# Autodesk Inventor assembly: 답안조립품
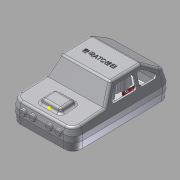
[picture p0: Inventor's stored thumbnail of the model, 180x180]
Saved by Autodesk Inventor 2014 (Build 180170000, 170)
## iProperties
Created: 2015-05
Part Number: 답안조립품
Document SubType Name: Assembly
Designer: Administrator
Author: Administrator
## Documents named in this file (13)
- C:\Documents and Settings\Administrator\바탕 화면\450508V1039\답안조립품.iam
- C:\Documents and Settings\Administrator\바탕 화면\450508V1039\본체.ipt
- C:\Documents and Settings\Administrator\바탕 화면\450508V1039\바퀴.ipt
- C:\Documents and Settings\Administrator\바탕 화면\450508V1039\커버.ipt
- C:\Documents and Settings\Administrator\바탕 화면\450508V1039\바퀴고정부.ipt
- C:\Documents and Settings\Administrator\바탕 화면\450508V1039\M2x4.ipt
- C:\Documents and Settings\Administrator\바탕 화면\450508V1039\바퀴고정부_MIR.ipt
- C:\Documents and Settings\Administrator\바탕 화면\450508V1039\M2x4_MIR.ipt
- C:\Documents and Settings\Administrator\바탕 화면\450508V1039\바퀴_MIR.ipt
- C:\Documents and Settings\Administrator\바탕 화면\450508V1039\바퀴고정부_MIR1.ipt
- C:\Documents and Settings\Administrator\바탕 화면\450508V1039\M2x4_MIR1.ipt
- C:\Documents and Settings\Administrator\바탕 화면\450508V1039\바퀴고정부_MIR_MIR.ipt
- C:\Documents and Settings\Administrator\바탕 화면\450508V1039\M2x4_MIR_MIR.ipt
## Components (16 placed, 4 different names)
1. M2x4:1
2. M2x4:2
3. M2x4:3
4. M2x4:4
5. M2x4_MIR:1
6. M2x4_MIR:2
7. M2x4_MIR:3
8. M2x4_MIR:4
9. M2x4_MIR1:1
10. M2x4_MIR1:2
11. M2x4_MIR1:3
12. M2x4_MIR1:4
13. M2x4_MIR_MIR:1
14. M2x4_MIR_MIR:2
15. M2x4_MIR_MIR:3
16. M2x4_MIR_MIR:4
